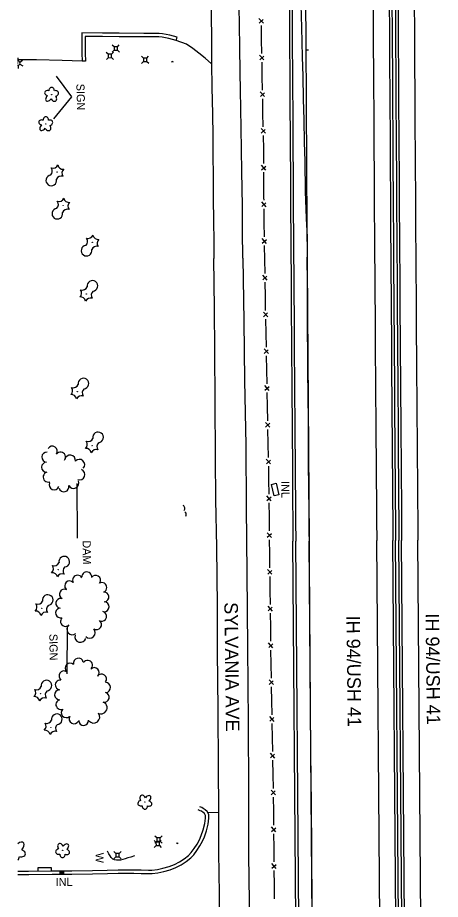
# Model space of a CAD drawing. Extents: x 588843 to 2552415, y 180129 to 269402.
# Drawn here: x 593743 to 594056, y 182464 to 183118 of the extents above; entities that cross this region are included whole.
import ezdxf

# ---------------------------------------------------------------- set-up
doc = ezdxf.new("R2010")
doc.units = 0
for name, color, linetype in [('Default', 7, 'Continuous'), ('E_DRN', 7, 'Continuous'), ('E_DRN_Text', 7, 'Continuous'), ('E_DWY', 7, 'Continuous'), ('E_FEN_P', 7, 'Continuous'), ('E_LAND_TreeLine_P', 7, 'Continuous'), ('E_LAND_Vegetation', 7, 'Continuous'), ('E_LTG', 7, 'Continuous'), ('E_PATH_Sidewalk', 7, 'Continuous'), ('E_RDWY', 7, 'Continuous'), ('E_RDWY_Gravel', 7, 'Continuous'), ('E_RDWY_Text', 7, 'Continuous'), ('E_SGN', 7, 'Continuous'), ('E_SGN_Text', 7, 'Continuous'), ('E_STRUCT_Text', 7, 'Continuous'), ('E_UTL_AG_Bold', 7, 'Continuous'), ('E_WAL', 7, 'Continuous'), ('E_WAL_Text', 7, 'Continuous'), ('P_RDWY_BarrierConc', 7, 'Continuous'), ('P_RDWY_PavtEdge', 7, 'Continuous')]:
    doc.layers.add(name, color=color, linetype=linetype)

# ---------------------------------------------------------------- blocks, each defined once
blk = doc.blocks.new('DAM')
at = {"layer": 'Default'}
blk.add_text('DAM', height=12, dxfattribs=at).set_placement((-19, -6))
blk = doc.blocks.new('CULV2')
at = {"layer": 'E_DRN'}
blk.add_arc((19.7, 14.8), 24.6, 216.8699, 323.1301, dxfattribs=at)
blk = doc.blocks.new('INLO')
at = {"layer": 'E_DRN'}
for p, q in [((2, -4), (2, 0)), ((4, -4), (4, 0)), ((6, -2), (0, -2))]:
    blk.add_line(p, q, dxfattribs=at)
blk.add_lwpolyline([(0, -4), (6, -4), (6, 0), (0, 0), (0, -4)], close=True, dxfattribs=at)
blk = doc.blocks.new('INLT_11')
at = {"layer": 'E_DRN_Text'}
blk.add_text('INL', height=12, dxfattribs=at).set_placement((-11, -6))
blk = doc.blocks.new('W_6')
at = {"layer": 'E_WAL_Text'}
blk.add_text('W', height=12, dxfattribs=at).set_placement((-4.5, -6))
blk = doc.blocks.new('INLT_12')
at = {"layer": 'E_DRN_Text'}
blk.add_text('INL', height=12, dxfattribs=at).set_placement((-11, -6))
blk = doc.blocks.new('SIGN')
at = {"layer": 'Default'}
blk.add_text('SIGN', height=12, dxfattribs=at).set_placement((-18.5, -6))
blk = doc.blocks.new('PED')
at = {"layer": 'Default'}
for p, q in [((-2.5, 2.5), (-5.3, 5.3)), ((2.5, 2.5), (5.3, 5.3)), ((-2.5, -2.5), (-5.3, -5.3)), ((2.5, -2.5), (5.3, -5.3))]:
    blk.add_line(p, q, dxfattribs=at)
blk.add_lwpolyline([(-2.5, -2.5), (2.5, -2.5), (2.5, 2.5), (-2.5, 2.5)], close=True, dxfattribs=at)
blk = doc.blocks.new('DTRE')
at = {"layer": 'Default'}
blk.add_circle((-0.2, 0), 0.183, dxfattribs=at)
for centre, major_axis, ratio in [((-5.9, 0.2), (4.93, -0.12), 0.832022), ((-1.9, 5.3), (1.36, -4.98), 0.782863), ((4.1, 2.7), (-5.27, -2.93), 0.691916), ((-2.5, -5.2), (1.8, 4.86), 0.716896), ((3.5, -3.7), (-5.01, 4.58), 0.560249)]:
    blk.add_ellipse(centre, major_axis=major_axis, ratio=ratio, start_param=1.570796, end_param=4.712389, dxfattribs=at)
blk = doc.blocks.new('CTRE')
at = {"layer": 'Default'}
blk.add_circle((0, 0), 0.223, dxfattribs=at)
for centre, start, end in [((-12, 9), 280.2067, 5.9716), ((-13.8, -5.9), 340.2113, 65.9762), ((1.8, 14.9), 220.2113, 305.9762), ((13.8, 5.9), 160.2113, 245.9762), ((-1.8, -14.9), 40.2113, 125.9762), ((12, -9), 185.9272, 100.2511)]:
    blk.add_arc(centre, 7.87, start, end, dxfattribs=at)

msp = doc.modelspace()

# ---------------------------------------------------------------- linework, layer by layer
at = {"layer": 'E_DRN'}
msp.add_lwpolyline([(593932.58, 182763.26), (593930.59, 182771.74), (593934.06, 182772.54), (593936.05, 182764.06), (593932.58, 182763.26)], close=True, dxfattribs=at)
at = {"layer": 'E_DWY'}
for points in [[(593860.58, 183103.1), (593855.16, 183104.58), (593849.82, 183105.53), (593847.26, 183105.78), (593835.89, 183105.8), (593817.74, 183105.95), (593805.49, 183106.15), (593790.08, 183106.2), (593790.12, 183091.21), (593790.19, 183085.19)], [(593859.92, 183100.69), (593854.61, 183102.14), (593849.48, 183103.05), (593847.13, 183103.28), (593835.87, 183103.3), (593817.71, 183103.45), (593805.47, 183103.65), (593792.59, 183103.69), (593792.62, 183091.22), (593792.69, 183085.22)], [(593886.08, 183083.27), (593881.33, 183087.56), (593876.78, 183091.25), (593872.34, 183094.62), (593867.57, 183097.88), (593859.92, 183100.69), (593860.58, 183103.1)], [(593792.69, 183085.22), (593790.19, 183085.19), (593775.47, 183085.77), (593756.48, 183086.18), (593742.51, 183086.17)], [(593742.55, 182482.68), (593750.69, 182482.76), (593768.21, 182482.91), (593776.72, 182483.04), (593782.56, 182482.99), (593797.9, 182483.24), (593809.01, 182483.44), (593816.98, 182483.66), (593823.33, 182483.74), (593828.52, 182483.7), (593833.9, 182483.59), (593839.43, 182483.52), (593842.05, 182483.51), (593846.39, 182483.96), (593850.72, 182484.87), (593855.45, 182486.26), (593859.78, 182487.89), (593863.72, 182489.9), (593867.33, 182492.29), (593870.76, 182495.02), (593872.91, 182497.34), (593875.28, 182500.46), (593877.54, 182503.89), (593879.42, 182507.35), (593880.83, 182510.58), (593882.38, 182515.03), (593883.56, 182520.11), (593884.17, 182524.36), (593884.03, 182527.13), (593882.96, 182529.3), (593881.52, 182530.71), (593879.98, 182531.71), (593878.95, 182532.26), (593877.41, 182532.98)], [(593742.56, 182485.18), (593750.67, 182485.26), (593768.18, 182485.41), (593776.71, 182485.54), (593782.55, 182485.49), (593797.85, 182485.74), (593808.95, 182485.94), (593816.93, 182486.16), (593823.32, 182486.24), (593828.55, 182486.2), (593833.95, 182486.09), (593839.45, 182486.02), (593841.93, 182486.01), (593846, 182486.43), (593850.11, 182487.3), (593854.66, 182488.63), (593858.76, 182490.18), (593862.46, 182492.07), (593865.86, 182494.31), (593869.06, 182496.86), (593870.99, 182498.94), (593873.23, 182501.91), (593875.39, 182505.18), (593877.17, 182508.44), (593878.5, 182511.5), (593879.98, 182515.73), (593881.1, 182520.57), (593881.66, 182524.48), (593881.56, 182526.49), (593880.9, 182527.81), (593879.94, 182528.75), (593878.71, 182529.55), (593877.83, 182530.02), (593876.35, 182530.72)], [(593883.23, 182528.74), (593891.54, 182528.8)]]:
    msp.add_lwpolyline(points, dxfattribs=at)
at = {"layer": 'E_FEN_P'}
for p, q in [((593924.51, 183113.37), (593921.29, 183116.93)), ((593921.36, 183113.48), (593924.39, 183116.26)), ((593924.97, 183086.19), (593921.76, 183089.75)), ((593921.82, 183086.3), (593924.85, 183089.08)), ((593925.45, 183059.02), (593922.23, 183062.57)), ((593922.3, 183059.12), (593925.32, 183061.91)), ((593926.01, 183031.85), (593922.79, 183035.4)), ((593922.86, 183031.95), (593925.89, 183034.73)), ((593926.36, 183004.65), (593923.19, 183008.25)), ((593923.21, 183004.8), (593926.28, 183007.53)), ((593926.53, 182977.48), (593923.34, 182981.05)), ((593923.38, 182977.6), (593926.43, 182980.36)), ((593926.88, 182950.3), (593923.69, 182953.87)), ((593923.73, 182950.42), (593926.78, 182953.18)), ((593927.3, 182923.09), (593924.08, 182926.66)), ((593924.14, 182923.2), (593927.18, 182925.98)), ((593927.76, 182895.85), (593924.54, 182899.42)), ((593924.6, 182895.96), (593927.64, 182898.74)), ((593928.3, 182868.62), (593925.07, 182872.18)), ((593925.14, 182868.72), (593928.17, 182871.51)), ((593928.83, 182841.38), (593925.61, 182844.94)), ((593925.68, 182841.48), (593928.71, 182844.27)), ((593929.37, 182814.13), (593926.15, 182817.7)), ((593926.21, 182814.24), (593929.25, 182817.03)), ((593929.91, 182786.89), (593926.68, 182790.45)), ((593926.75, 182787), (593929.79, 182789.78)), ((593930.29, 182759.64), (593927.09, 182763.23)), ((593927.13, 182759.77), (593930.19, 182762.53)), ((593930.58, 182732.4), (593927.39, 182735.98)), ((593927.43, 182732.53), (593930.49, 182735.29)), ((593930.88, 182705.15), (593927.69, 182708.74)), ((593927.73, 182705.28), (593930.79, 182708.04)), ((593931.24, 182677.91), (593928.04, 182681.49)), ((593928.09, 182678.04), (593931.14, 182680.8)), ((593931.61, 182650.67), (593928.41, 182654.25)), ((593928.46, 182650.79), (593931.51, 182653.56)), ((593931.98, 182623.43), (593928.78, 182627.01)), ((593928.83, 182623.55), (593931.88, 182626.32)), ((593932.47, 182596.19), (593929.25, 182599.76)), ((593929.31, 182596.3), (593932.35, 182599.08)), ((593932.97, 182568.95), (593929.75, 182572.52)), ((593929.81, 182569.06), (593932.85, 182571.84)), ((593933.46, 182541.71), (593930.24, 182545.28)), ((593930.31, 182541.82), (593933.35, 182544.6)), ((593933.8, 182514.45), (593930.62, 182518.05)), ((593930.64, 182514.59), (593933.71, 182517.34)), ((593934.01, 182487.21), (593930.83, 182490.81)), ((593930.85, 182487.35), (593933.92, 182490.1))]:
    msp.add_line(p, q, dxfattribs=at)
for points in [[(593923.26, 183101.37), (593923.08, 183111.75)], [(593923.43, 183091), (593923.26, 183101.37)], [(593923.72, 183074.2), (593923.54, 183084.57)], [(593923.9, 183063.82), (593923.9, 183063.86), (593923.72, 183074.2)], [(593924.24, 183047.02), (593924.03, 183057.4)], [(593924.46, 183036.64), (593924.24, 183047.02)], [(593924.81, 183019.84), (593924.59, 183030.22)], [(593924.88, 183009.47), (593924.85, 183018), (593924.81, 183019.84)], [(593924.95, 182992.66), (593924.91, 183003.04)], [(593925.01, 182982.29), (593924.99, 182984.04), (593924.95, 182992.66)], [(593925.23, 182965.49), (593925.1, 182975.86)], [(593925.36, 182955.11), (593925.23, 182965.49)], [(593925.58, 182938.31), (593925.45, 182948.68)], [(593925.76, 182927.91), (593925.58, 182938.31)], [(593926.04, 182911.07), (593925.87, 182921.47)], [(593926.22, 182900.66), (593926.04, 182911.07)], [(593926.54, 182883.82), (593926.33, 182894.23)], [(593926.74, 182873.42), (593926.54, 182883.82)], [(593927.08, 182856.58), (593926.87, 182866.99)], [(593927.28, 182846.18), (593927.08, 182856.58)], [(593927.61, 182829.34), (593927.41, 182839.75)], [(593927.82, 182818.94), (593927.61, 182829.34)], [(593928.15, 182802.1), (593927.95, 182812.51)], [(593928.36, 182791.7), (593928.15, 182802.1)], [(593928.66, 182774.86), (593928.62, 182778.4), (593928.49, 182785.27)], [(593928.77, 182764.46), (593928.66, 182774.86)], [(593928.96, 182747.62), (593928.85, 182758.02)], [(593929.07, 182737.22), (593928.96, 182747.62)], [(593929.26, 182720.38), (593929.14, 182730.78)], [(593929.37, 182709.97), (593929.26, 182720.38)], [(593929.58, 182693.13), (593929.47, 182701.53), (593929.44, 182703.53)], [(593929.72, 182682.73), (593929.58, 182693.13)], [(593929.95, 182665.89), (593929.81, 182676.29)], [(593930.09, 182655.49), (593929.95, 182665.89)], [(593930.32, 182638.65), (593930.18, 182649.05)], [(593930.46, 182628.25), (593930.32, 182638.65)], [(593930.74, 182611.41), (593930.55, 182621.62), (593930.55, 182621.81)], [(593930.93, 182601), (593930.74, 182611.41)], [(593931.23, 182584.16), (593931.04, 182594.57)], [(593931.42, 182573.76), (593931.23, 182584.16)], [(593931.73, 182556.92), (593931.54, 182567.32)], [(593931.92, 182546.52), (593931.73, 182556.92)], [(593932.22, 182529.68), (593932.04, 182540.08)], [(593932.31, 182519.28), (593932.22, 182529.68), (593932.22, 182529.68)], [(593932.44, 182502.44), (593932.36, 182512.84)], [(593932.52, 182492.04), (593932.44, 182502.44)], [(593932.65, 182475.19), (593932.57, 182485.6)], [(593932.73, 182464.79), (593932.65, 182475.19)]]:
    msp.add_lwpolyline(points, dxfattribs=at)
at = {"layer": 'E_LAND_TreeLine_P'}
for centre, radius, start, end in [((593768.2, 182796.33), 3.73, 326.505, 146.505), ((593764.16, 182791.93), 3.73, 87.21611, 267.21611), ((593774.25, 182791.98), 3.73, 323.53736, 143.53736), ((593781.4, 182789.56), 3.93, 350.76373, 170.76373), ((593763.97, 182784.48), 3.73, 90.4872, 270.4872), ((593788.24, 182786.38), 3.93, 318.14634, 138.14634), ((593765.14, 182777.2), 3.73, 107.13391, 287.13391), ((593788.43, 182779), 3.93, 249.60923, 69.60923), ((593769.65, 182771.52), 3.73, 157.16002, 337.16002), ((593776.8, 182770.03), 3.73, 195.2411, 15.2411), ((593783.94, 182772.72), 3.93, 205.85294, 25.85294), ((593793.7, 182703.26), 3.66, 1.78944, 181.78944), ((593781.01, 182696.55), 3.66, 43.63412, 223.63412), ((593786.91, 182700.79), 3.66, 29.69353, 209.69353), ((593800.21, 182700.76), 3.66, 325.53085, 145.53085), ((593804.84, 182695.36), 3.66, 298.70631, 118.70631), ((593777.12, 182690.44), 3.66, 61.81765, 241.81765), ((593774.44, 182683.65), 3.66, 81.85296, 261.85296), ((593806.52, 182688.33), 3.66, 277.99266, 97.99266), ((593774.31, 182676.48), 3.66, 106.38686, 286.38686), ((593806.55, 182681.04), 3.66, 268.50685, 88.50685), ((593804.79, 182673.95), 3.66, 255.62647, 75.62647), ((593777.93, 182670.24), 3.66, 134.21262, 314.21262), ((593783.07, 182664.42), 4.12, 129.0159, 309.0159), ((593800.94, 182667.8), 3.66, 234.98202, 54.98202), ((593789.04, 182658.87), 4.12, 163.27552, 343.27552), ((593795.92, 182661.9), 4.12, 224.7201, 44.7201), ((593787.52, 182639.28), 3.67, 13.31574, 193.31574), ((593794.34, 182637.71), 3.67, 324.36283, 144.36283), ((593781.31, 182635.64), 3.67, 46.1121, 226.1121), ((593799.21, 182632.31), 3.67, 314.77988, 134.77988), ((593776.79, 182629.89), 3.67, 55.43379, 235.43379), ((593804.68, 182627.47), 3.67, 325.02397, 145.02397), ((593774.08, 182623.14), 3.67, 84.01199, 264.01199), ((593807.69, 182621.23), 3.67, 272.71556, 92.71556), ((593773.59, 182615.84), 3.67, 94.37414, 274.37414), ((593806.74, 182614.04), 3.67, 256.20945, 76.20945), ((593774.53, 182608.63), 3.67, 114.84735, 294.84735), ((593804.28, 182606.27), 4.49, 249.41931, 69.41931), ((593778.54, 182602.59), 3.67, 131.94577, 311.94577), ((593798.86, 182599.41), 4.49, 217.57383, 37.57383), ((593784.29, 182598.1), 3.67, 151.47913, 331.47913), ((593791.39, 182596.87), 3.67, 182.32469, 2.32469)]:
    msp.add_arc(centre, radius, start, end, dxfattribs=at)
at = {"layer": 'E_LAND_Vegetation'}
for centre, major_axis, ratio, start_param, end_param in [((593743.59, 182502.8), (-3.18, -3.53), 0.560249, 1.570796, 4.42957), ((593744.7, 182498.59), (-3.41, 1.23), 0.716896, 1.570796, 4.712389), ((593740.94, 182496.19), (0.06, 3.45), 0.832022, 3.761924, 4.712389)]:
    msp.add_ellipse(centre, major_axis=major_axis, ratio=ratio, start_param=start_param, end_param=end_param, dxfattribs=at)
at = {"layer": 'E_LTG'}
for p, q in [((593742.67, 183087.82), (593742.74, 183085.32)), ((593744.06, 183084.61), (593746.19, 183085.92)), ((593742.82, 183082.33), (593742.89, 183079.83)), ((593744.1, 183083.11), (593746.3, 183081.92))]:
    msp.add_line(p, q, dxfattribs=at)
msp.add_circle((593742.78, 183083.82), 0.125, dxfattribs=at)
msp.add_arc((593742.78, 183083.82), 1.5, 260.26645, 100.13217, dxfattribs=at)
at = {"layer": 'E_PATH_Sidewalk'}
msp.add_lwpolyline([(593767.5, 182485.4), (593767.5, 182487.69), (593757.38, 182487.56), (593757.45, 182485.32)], dxfattribs=at)
at = {"layer": 'E_RDWY'}
for points in [[(593885.75, 183125.82), (593885.83, 183117.03), (593886.02, 183104.25), (593886.08, 183083.59), (593886.36, 183065.86), (593886.8, 183046.28), (593887, 183029.74), (593887.14, 183014.9), (593887.33, 183001.01), (593887.46, 182982.69), (593887.66, 182967.87), (593887.89, 182950.87), (593887.92, 182939.09)], [(593909.31, 182939.34), (593909.13, 182959.36), (593908.95, 182977.55), (593908.88, 182991.11), (593908.62, 183003.24), (593908.21, 183020.07), (593907.99, 183035.5), (593907.82, 183050.31), (593907.7, 183063.61), (593907.46, 183077.26), (593907.1, 183095.74), (593906.95, 183111.92), (593906.71, 183125.83)], [(593892.83, 182339.74), (593892.47, 182371.81), (593892.35, 182410.49), (593892.28, 182438.95), (593891.95, 182468.41), (593891.65, 182498.96), (593891.53, 182530.11), (593891.28, 182562.07), (593890.99, 182604.95), (593890.64, 182647.93), (593890.5, 182681.62), (593890.05, 182725.22), (593889.29, 182760.42), (593889.1, 182791.5), (593888.84, 182833.44), (593888.64, 182870.47), (593888.32, 182902.13), (593887.92, 182939.09)], [(593909.31, 182939.34), (593909.99, 182892.76), (593910.48, 182848.81), (593911.43, 182800.87), (593911.87, 182754.87), (593912.37, 182705.86), (593912.78, 182650.87), (593913.19, 182595.54), (593913.47, 182544.23), (593913.6, 182497.19), (593914.37, 182445.23), (593914.53, 182398.22), (593914.66, 182370.76), (593915.11, 182338.51)]]:
    msp.add_lwpolyline(points, dxfattribs=at)
at = {"layer": 'E_RDWY_Gravel'}
for points in [[(593952.39, 183127.13), (593952.79, 183110.13), (593953.32, 183088.56), (593953.72, 183074.11), (593954.1, 183057.08), (593954.48, 183041.8), (593954.81, 183025.03), (593955.13, 183011.45), (593955.55, 182988.49), (593955.95, 182975.9), (593956.35, 182968.4), (593956.9, 182955.23), (593957, 182940.14)], [(593961.64, 182331.65), (593961.27, 182366.32), (593961.01, 182415.15), (593960.66, 182458.51), (593960.31, 182500.45), (593960.09, 182534.66), (593959.79, 182572.79), (593959.48, 182607.03), (593959.14, 182643.74), (593958.92, 182677.5), (593958.62, 182714.32), (593958.48, 182751.45), (593958.07, 182787.03), (593957.85, 182818.62), (593957.54, 182856.48), (593957.32, 182897.87), (593957.27, 182920.34), (593957, 182940.14)]]:
    msp.add_lwpolyline(points, dxfattribs=at)
at = {"layer": 'E_SGN'}
msp.add_line((593779.28, 182666.11), (593779, 182631.49), dxfattribs=at)
for points in [[(593782.61, 183058.8), (593771.33, 183074.15)], [(593769.28, 183042.66), (593782.61, 183058.8)]]:
    msp.add_lwpolyline(points, dxfattribs=at)
at = {"layer": 'E_WAL'}
for points in [[(593786.77, 182731.89), (593786.69, 182772.32)], [(593829.02, 182496.66), (593826.26, 182495.67), (593824.23, 182495.03), (593822.13, 182494.41), (593820.34, 182493.91), (593818.68, 182493.46), (593817.13, 182493.23), (593815.79, 182493.23), (593814.18, 182493.48), (593812.91, 182494.21), (593811.84, 182495.21), (593810.99, 182496.45), (593810.13, 182497.94), (593809.18, 182500)]]:
    msp.add_lwpolyline(points, dxfattribs=at)
at = {"layer": 'P_RDWY_BarrierConc'}
for p, q in [((593950.9, 182168.4), (593946.46, 182729.59)), ((593952.9, 182168.42), (593948.46, 182729.6)), ((594024.9, 182168.99), (594020.46, 182730.17)), ((594026.9, 182169), (594022.46, 182730.19)), ((594029.4, 182169.02), (594024.96, 182730.21)), ((594031.4, 182169.04), (594026.96, 182730.23))]:
    msp.add_line(p, q, dxfattribs=at)
for radius, start in [(171884.59, 180.1287302), (171882.59, 180.1287302), (171880.09, 180.1287302), (171878.09, 180.1287302), (171958.59, 180.290989), (171956.59, 180.290989)]:
    msp.add_arc((765899.68, 184089.33), radius, start, 180.4530652, dxfattribs=at)
at = {"layer": 'P_RDWY_PavtEdge'}
for p, q in [((593955.97, 183093.61), (593957.97, 183093.62)), ((593962.9, 182168.5), (593958.46, 182729.68)), ((594012.9, 182168.89), (594008.46, 182730.08)), ((594043.4, 182169.14), (594038.96, 182730.32))]:
    msp.add_line(p, q, dxfattribs=at)
for radius, start, end in [(171896.59, 180.1287302, 180.4530652), (171866.09, 180.1287302, 180.4530652), (171946.59, 180.3112583, 180.3317952), (171946.59, 180.3317952, 180.4530652)]:
    msp.add_arc((765899.68, 184089.33), radius, start, end, dxfattribs=at)

# ---------------------------------------------------------------- block references
at = {"layer": 'E_DRN'}
for name, p, xscale, yscale, rotation in [('CULV2', (593857.87, 183084.63), 0.035372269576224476, 0.035372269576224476, 178.03677634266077), ('CULV2', (593865.88, 182752.48), 0.09341770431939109, 0.09341770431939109, 102.09932894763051), ('CULV2', (593866.98, 182748.23), 0.07658720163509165, 0.07658720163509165, 103.24509177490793), ('CULV2', (593860.09, 182506.13), 0.03675805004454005, 0.036758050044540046, 2.506194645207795), ('INLO', (593776.81, 182483.04), 0.49999999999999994, 0.5, -179.15518749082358)]:
    msp.add_blockref(name, p, dxfattribs=dict(at, xscale=xscale, yscale=yscale, rotation=rotation))
at = {"layer": 'E_DRN_Text'}
for name, p, xscale, yscale, rotation in [('INLT_12', (593940.85, 182768.7), 0.49999999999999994, 0.49999999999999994, -89.28375254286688), ('INLT_11', (593776.19, 182477.22), 0.5, 0.5000000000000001, 0.8448125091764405)]:
    msp.add_blockref(name, p, dxfattribs=dict(at, xscale=xscale, yscale=yscale, rotation=rotation))
at = {"layer": 'E_LAND_Vegetation'}
for name, p, xscale, yscale, rotation in [('DTRE', (593767.69, 183060.37), 0.5, 0.5, -88.44006292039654), ('DTRE', (593763.36, 183038.61), 0.5, 0.5, -88.44006292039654), ('CTRE', (593771.76, 183003.1), 0.5, 0.5, -88.44006292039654), ('CTRE', (593776.23, 182978.43), 0.5, 0.5, -88.44006292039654), ('CTRE', (593797.85, 182951.05), 0.5, 0.5, -88.44006292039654), ('CTRE', (593793.47, 182912.78), 0.5000000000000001, 0.5000000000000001, 90.45304071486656), ('CTRE', (593786.79, 182840.41), 0.5000000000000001, 0.5000000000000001, 90.45304071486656), ('CTRE', (593797.65, 182800.52), 0.5000000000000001, 0.5000000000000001, 90.45304071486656), ('CTRE', (593772.59, 182708.47), 0.5000000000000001, 0.5000000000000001, 90.45304071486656), ('CTRE', (593760.36, 182680.02), 0.5000000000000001, 0.5000000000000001, 90.45304071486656), ('CTRE', (593759.43, 182616.64), 0.5000000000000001, 0.5000000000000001, 90.45304071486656), ('CTRE', (593767.11, 182591.77), 0.5000000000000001, 0.5000000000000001, 90.45304071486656), ('DTRE', (593836.76, 182536.58), 0.5000000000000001, 0.5000000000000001, 90.45304071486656), ('DTRE', (593775.85, 182500.75), 0.5000000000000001, 0.5000000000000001, 90.45304071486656)]:
    msp.add_blockref(name, p, dxfattribs=dict(at, xscale=xscale, yscale=yscale, rotation=rotation))
at = {"layer": 'E_SGN_Text'}
for p, xscale, yscale, rotation in [((593789.23, 183059.33), 0.5, 0.5, -88.44006292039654), ((593769.11, 182651.71), 0.49999999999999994, 0.49999999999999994, -89.28375254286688)]:
    msp.add_blockref('SIGN', p, dxfattribs=dict(at, xscale=xscale, yscale=yscale, rotation=rotation))
at = {"layer": 'E_STRUCT_Text', "xscale": 0.49999999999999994, "yscale": 0.49999999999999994, "rotation": -89.28375254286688}
msp.add_blockref('DAM', (593793.75, 182720.79), dxfattribs=at)
at = {"layer": 'E_UTL_AG_Bold'}
for p, xscale, yscale, rotation in [((593810.86, 183089.15), 0.5, 0.5, -88.44006292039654), ((593815.18, 183094.62), 0.5, 0.5, -88.44006292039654), ((593836.92, 183086.36), 0.5, 0.5, -88.44006292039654), ((593846.86, 182508.57), 0.49999999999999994, 0.49999999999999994, 90.71624745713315), ((593846.24, 182505.42), 0.49999999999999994, 0.49999999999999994, 90.71624745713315), ((593816.47, 182497.06), 0.49999999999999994, 0.49999999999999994, 90.71624745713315)]:
    msp.add_blockref('PED', p, dxfattribs=dict(at, xscale=xscale, yscale=yscale, rotation=rotation))
at = {"layer": 'E_WAL_Text', "xscale": 0.49999999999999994, "yscale": 0.49999999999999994, "rotation": -89.28375254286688}
msp.add_blockref('W_6', (593803.26, 182496.59), dxfattribs=at)

# ---------------------------------------------------------------- texts
at = {"layer": 'E_RDWY_Text'}
for s, p in [('SYLVANIA AVE', (593895.61, 182684.39)), ('IH 94/USH 41', (593986.01, 182674.47)), ('IH 94/USH 41', (594044.62, 182676.09))]:
    msp.add_text(s, height=10, rotation=270.72826, dxfattribs=at).set_placement(p)

doc.saveas('drawing.dxf')
